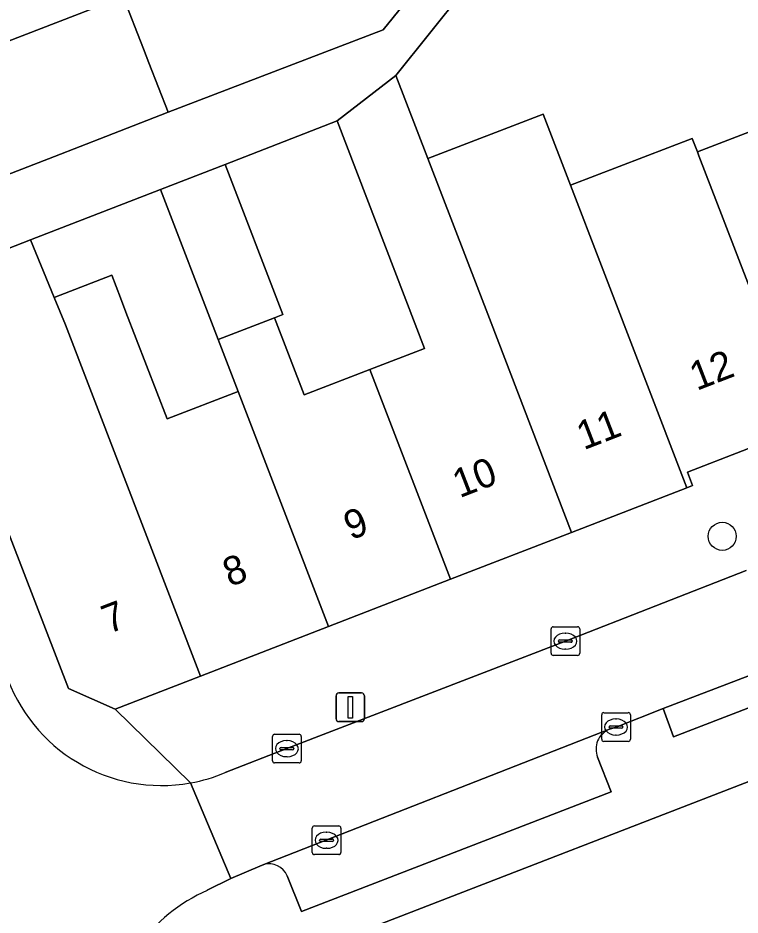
# Model space of a CAD drawing. Extents: x 161692 to 162379, y 380760 to 381678.
# Drawn here: x 161861.55 to 161886.75, y 381122.22 to 381153.51 of the extents above; entities that cross this region are included whole.
import ezdxf

# ---------------------------------------------------------------- set-up
doc = ezdxf.new("R2010")
doc.units = 0
for name, color, linetype in [('IMGEO_Boom', 7, 'Continuous'), ('IMGEO_Erf', 7, 'Continuous'), ('IMGEO_Groenvoorziening', 7, 'Continuous'), ('IMGEO_Kolk', 7, 'Continuous'), ('IMGEO_Lichtmast', 7, 'Continuous'), ('IMGEO_Pand', 7, 'Continuous'), ('IMGEO_Pand_nummerreeks', 7, 'Continuous'), ('IMGEO_Parkeervlak_open', 7, 'Continuous'), ('IMGEO_Rijbaan_lokaal_open', 7, 'Continuous'), ('IMGEO_Voetpad_gesloten', 7, 'Continuous'), ('IMGEO_Voetpad_open', 7, 'Continuous')]:
    doc.layers.add(name, color=color, linetype=linetype)

msp = doc.modelspace()

# ---------------------------------------------------------------- linework, layer by layer
at = {"layer": 'IMGEO_Boom'}
msp.add_circle((161886.126, 381135.429), 0.489, dxfattribs=at)
at = {"layer": 'IMGEO_Erf'}
for points in [[(161865.216, 381154.264), (161865.926, 381152.436), (161866.117, 381151.943), (161866.786, 381150.22), (161874.298, 381153.095), (161886.039, 381167.594)], [(161879.432, 381157.38), (161874.741, 381151.504), (161875.854, 381148.61), (161879.878, 381150.157), (161880.833, 381147.673), (161885.082, 381149.306), (161885.262, 381148.838), (161889.585, 381150.509), (161891.5, 381151.249), (161891.788, 381151.36), (161893.937, 381152.191), (161893.123, 381154.298)]]:
    msp.add_lwpolyline(points, dxfattribs=at)
for points in [[(161872.684, 381149.919), (161868.775, 381148.403), (161870.787, 381143.167), (161870.498, 381143.055), (161871.535, 381140.359), (161873.832, 381141.247), (161875.736, 381141.983)], [(161866.523, 381147.53), (161861.984, 381145.77), (161862.817, 381143.761), (161864.821, 381144.537), (161865.126, 381143.748), (161865.318, 381143.252), (161866.76, 381139.523), (161869.234, 381140.479), (161868.535, 381142.297)]]:
    msp.add_lwpolyline(points, close=True, dxfattribs=at)
at = {"layer": 'IMGEO_Groenvoorziening'}
msp.add_lwpolyline([(161889.237, 381098.122), (161887.481, 381099.78), (161889.509, 381119.184), (161891.249, 381120.655), (161892.607, 381122.097), (161890.302, 381128.132), (161871.724, 381120.949), (161866.545, 381106.35), (161863.772, 381105.601), (161863.248, 381101.216), (161862.407, 381093.385), (161863.41, 381093.267), (161863.195, 381091.592), (161862.202, 381091.684), (161860.9, 381080.876), (161860.594, 381078.32), (161862.509, 381077.782), (161863.62, 381075.409), (161863.759, 381073.519), (161864.131, 381072.768), (161864.237, 381067.43), (161859.466, 381070.205)], dxfattribs=at)
at = {"layer": 'IMGEO_Kolk'}
for p, q in [((161880.227, 381132.274), (161881.079, 381132.274)), ((161880.152, 381131.348), (161880.152, 381132.2)), ((161880.64, 381132.054), (161880.665, 381132.054)), ((161881.153, 381132.2), (161881.153, 381131.348)), ((161880.411, 381131.768), (161880.411, 381131.78)), ((161880.849, 381131.731), (161880.451, 381131.731)), ((161880.454, 381131.817), (161880.852, 381131.817)), ((161880.895, 381131.78), (161880.895, 381131.768)), ((161880.663, 381131.494), (161880.638, 381131.494)), ((161881.079, 381131.274), (161880.227, 381131.274)), ((161881.919, 381128.351), (161881.919, 381129.203)), ((161881.994, 381129.277), (161882.846, 381129.277)), ((161882.92, 381129.203), (161882.92, 381128.351)), ((161882.221, 381128.82), (161882.619, 381128.82)), ((161882.407, 381129.057), (161882.432, 381129.057)), ((161870.507, 381128.522), (161871.359, 381128.522)), ((161882.178, 381128.771), (161882.178, 381128.783)), ((161882.616, 381128.734), (161882.218, 381128.734)), ((161882.662, 381128.783), (161882.662, 381128.771)), ((161870.432, 381127.596), (161870.432, 381128.448)), ((161870.92, 381128.302), (161870.945, 381128.302)), ((161871.433, 381128.448), (161871.433, 381127.596)), ((161882.846, 381128.277), (161881.994, 381128.277)), ((161882.43, 381128.497), (161882.405, 381128.497)), ((161870.691, 381128.016), (161870.691, 381128.028)), ((161871.129, 381127.979), (161870.731, 381127.979)), ((161870.734, 381128.065), (161871.132, 381128.065)), ((161871.175, 381128.028), (161871.175, 381128.016)), ((161870.943, 381127.742), (161870.918, 381127.742)), ((161871.359, 381127.522), (161870.507, 381127.522)), ((161871.817, 381124.399), (161871.817, 381125.251)), ((161871.892, 381125.325), (161872.744, 381125.325)), ((161872.305, 381125.105), (161872.33, 381125.105)), ((161872.818, 381125.251), (161872.818, 381124.399)), ((161872.076, 381124.819), (161872.076, 381124.831)), ((161872.514, 381124.782), (161872.116, 381124.782)), ((161872.119, 381124.868), (161872.517, 381124.868)), ((161872.56, 381124.831), (161872.56, 381124.819)), ((161872.328, 381124.545), (161872.303, 381124.545)), ((161872.744, 381124.325), (161871.892, 381124.325))]:
    msp.add_line(p, q, dxfattribs=at)
for points in [[(161880.227, 381132.274), (161881.079, 381132.274)], [(161880.152, 381131.348), (161880.152, 381132.2)], [(161881.153, 381132.2), (161881.153, 381131.348)], [(161881.079, 381131.274), (161880.227, 381131.274)], [(161881.919, 381128.351), (161881.919, 381129.203)], [(161881.994, 381129.277), (161882.846, 381129.277)], [(161882.92, 381129.203), (161882.92, 381128.351)], [(161870.507, 381128.522), (161871.359, 381128.522)], [(161870.432, 381127.596), (161870.432, 381128.448)], [(161871.433, 381128.448), (161871.433, 381127.596)], [(161882.846, 381128.277), (161881.994, 381128.277)], [(161871.359, 381127.522), (161870.507, 381127.522)], [(161871.817, 381124.399), (161871.817, 381125.251)], [(161871.892, 381125.325), (161872.744, 381125.325)], [(161872.818, 381125.251), (161872.818, 381124.399)], [(161872.744, 381124.325), (161871.892, 381124.325)]]:
    msp.add_lwpolyline(points, dxfattribs=at)
for centre, radius, start, end in [((161880.229, 381132.198), 0.0765, 91.552, 178.448), ((161880.229, 381132.198), 0.0765, 91.552, 178.448), ((161881.077, 381132.198), 0.0765, 1.552, 88.448), ((161881.077, 381132.198), 0.0765, 1.552, 88.448), ((161880.451, 381131.777), 0.0403, 85.8775, 175.7526), ((161880.448, 381131.767), 0.0366, 178.938, 274.7102), ((161880.852, 381131.774), 0.043, 264.8664, 352.4533), ((161880.856, 381131.779), 0.0386, 1.7309, 96.639), ((161880.229, 381131.35), 0.0765, 181.552, 268.448), ((161880.229, 381131.35), 0.0765, 181.552, 268.448), ((161881.077, 381131.35), 0.0765, 271.552, 358.448), ((161881.077, 381131.35), 0.0765, 271.552, 358.448), ((161881.996, 381129.201), 0.0765, 91.552, 178.448), ((161881.996, 381129.201), 0.0765, 91.552, 178.448), ((161882.844, 381129.201), 0.0765, 1.552, 88.448), ((161882.844, 381129.201), 0.0765, 1.552, 88.448), ((161882.218, 381128.78), 0.0403, 85.8775, 175.7526), ((161882.623, 381128.782), 0.0386, 1.7309, 96.639), ((161870.509, 381128.446), 0.0765, 91.552, 178.448), ((161870.509, 381128.446), 0.0765, 91.552, 178.448), ((161871.357, 381128.446), 0.0765, 1.552, 88.448), ((161871.357, 381128.446), 0.0765, 1.552, 88.448), ((161882.215, 381128.77), 0.0366, 178.938, 274.7102), ((161882.619, 381128.777), 0.043, 264.8664, 352.4533), ((161881.996, 381128.353), 0.0765, 181.552, 268.448), ((161881.996, 381128.353), 0.0765, 181.552, 268.448), ((161882.844, 381128.353), 0.0765, 271.552, 358.448), ((161882.844, 381128.353), 0.0765, 271.552, 358.448), ((161870.731, 381128.025), 0.0403, 85.8775, 175.7526), ((161870.728, 381128.015), 0.0366, 178.938, 274.7102), ((161871.132, 381128.022), 0.043, 264.8664, 352.4533), ((161871.136, 381128.027), 0.0386, 1.7309, 96.639), ((161870.509, 381127.598), 0.0765, 181.552, 268.448), ((161870.509, 381127.598), 0.0765, 181.552, 268.448), ((161871.357, 381127.598), 0.0765, 271.552, 358.448), ((161871.357, 381127.598), 0.0765, 271.552, 358.448), ((161871.894, 381125.249), 0.0765, 91.552, 178.448), ((161871.894, 381125.249), 0.0765, 91.552, 178.448), ((161872.742, 381125.249), 0.0765, 1.552, 88.448), ((161872.742, 381125.249), 0.0765, 1.552, 88.448), ((161872.116, 381124.828), 0.0403, 85.8775, 175.7526), ((161872.113, 381124.818), 0.0366, 178.938, 274.7102), ((161872.517, 381124.825), 0.043, 264.8664, 352.4533), ((161872.521, 381124.83), 0.0386, 1.7309, 96.639), ((161871.894, 381124.401), 0.0765, 181.552, 268.448), ((161871.894, 381124.401), 0.0765, 181.552, 268.448), ((161872.742, 381124.401), 0.0765, 271.552, 358.448), ((161872.742, 381124.401), 0.0765, 271.552, 358.448)]:
    msp.add_arc(centre, radius, start, end, dxfattribs=at)
for centre, major_axis, ratio, start_param, end_param in [((161880.639, 381131.774), (-0.387, 0.002), 0.722429, 4.712389, 7.853982), ((161880.664, 381131.774), (-0.39, 0.002), 0.717154, 1.570796, 4.712389), ((161882.406, 381128.777), (-0.387, 0.002), 0.722429, 4.712389, 7.853982), ((161882.431, 381128.777), (-0.39, 0.002), 0.717154, 1.570796, 4.712389), ((161870.919, 381128.022), (-0.387, 0.002), 0.722429, 4.712389, 7.853982), ((161870.944, 381128.022), (-0.39, 0.002), 0.717154, 1.570796, 4.712389), ((161872.304, 381124.825), (-0.387, 0.002), 0.722429, 4.712389, 7.853982), ((161872.329, 381124.825), (-0.39, 0.002), 0.717154, 1.570796, 4.712389)]:
    msp.add_ellipse(centre, major_axis=major_axis, ratio=ratio, start_param=start_param, end_param=end_param, dxfattribs=at)
at = {"layer": 'IMGEO_Lichtmast'}
for p, q in [((161872.651, 381129.066), (161872.651, 381129.866)), ((161872.651, 381129.866), (161872.651, 381129.066)), ((161872.751, 381129.966), (161873.541, 381129.966)), ((161873.541, 381129.966), (161872.751, 381129.966)), ((161873.641, 381129.866), (161873.641, 381129.066)), ((161873.641, 381129.066), (161873.641, 381129.866)), ((161873.541, 381128.966), (161872.751, 381128.966)), ((161872.751, 381128.966), (161873.541, 381128.966))]:
    msp.add_line(p, q, dxfattribs=at)
msp.add_lwpolyline([(161873.071, 381129.841), (161873.221, 381129.841), (161873.221, 381129.091), (161873.071, 381129.091), (161873.071, 381129.841)], dxfattribs=at)
for centre, start, end in [((161872.751, 381129.866), 90, 180), ((161872.751, 381129.866), 90, 180), ((161873.541, 381129.866), 0, 90), ((161873.541, 381129.866), 360, 90), ((161872.751, 381129.066), 180, 270), ((161872.751, 381129.066), 180, 270), ((161873.541, 381129.066), 270, 0), ((161873.541, 381129.066), 270, 0)]:
    msp.add_arc(centre, 0.1, start, end, dxfattribs=at)
at = {"layer": 'IMGEO_Pand'}
for points in [[(161853.223, 381156.241), (161855.451, 381150.483), (161865.216, 381154.264), (161864.766, 381155.425), (161865.389, 381156.97), (161864.704, 381158.737), (161863.819, 381159.013), (161863.374, 381160.161), (161858.668, 381158.344)], [(161865.216, 381154.264), (161855.451, 381150.483), (161857.147, 381146.103), (161858.29, 381146.546), (161858.163, 381146.874), (161862.825, 381148.683), (161864.611, 381149.376), (161866.786, 381150.22), (161866.117, 381151.943), (161865.926, 381152.436)], [(161875.854, 381148.61), (161874.741, 381151.504), (161872.684, 381149.919), (161875.736, 381141.983), (161873.832, 381141.247), (161876.645, 381133.93), (161880.871, 381135.564), (161878.057, 381142.88)], [(161889.585, 381150.509), (161885.262, 381148.838), (161885.29, 381148.766), (161885.313, 381148.706), (161886.16, 381146.503), (161889.145, 381138.744), (161891.289, 381139.573), (161893.483, 381140.422), (161890.933, 381147.02), (161890.729, 381147.549)], [(161880.833, 381147.673), (161879.878, 381150.157), (161875.854, 381148.61), (161878.057, 381142.88), (161880.871, 381135.564), (161884.891, 381137.118), (161881.914, 381144.861)], [(161885.262, 381148.838), (161885.082, 381149.306), (161880.833, 381147.673), (161881.914, 381144.861), (161884.891, 381137.118), (161885.092, 381137.196), (161884.909, 381137.67), (161888.752, 381139.156), (161888.942, 381138.666), (161889.145, 381138.744), (161886.16, 381146.503), (161885.313, 381148.706), (161885.29, 381148.766)], [(161868.775, 381148.403), (161866.523, 381147.53), (161868.535, 381142.297), (161870.498, 381143.055), (161870.787, 381143.167)], [(161862.817, 381143.761), (161861.984, 381145.77), (161859.027, 381144.626), (161858.947, 381144.831), (161857.799, 381144.387), (161863.314, 381130.126), (161864.944, 381129.405), (161867.917, 381130.555), (161863.207, 381142.809)], [(161869.234, 381140.479), (161866.76, 381139.523), (161865.318, 381143.252), (161865.126, 381143.748), (161864.821, 381144.537), (161862.817, 381143.761), (161863.207, 381142.809), (161867.917, 381130.555), (161872.385, 381132.282)], [(161873.832, 381141.247), (161871.535, 381140.359), (161870.498, 381143.055), (161868.535, 381142.297), (161869.234, 381140.479), (161872.385, 381132.282), (161876.645, 381133.93)]]:
    msp.add_lwpolyline(points, close=True, dxfattribs=at)
at = {"layer": 'IMGEO_Parkeervlak_open'}
for points in [[(161882.194, 381128.7), (161870.125, 381123.977)], [(161882.245, 381126.518), (161881.772, 381127.73)], [(161870.947, 381123.585), (161871.442, 381122.337), (161882.245, 381126.518)]]:
    msp.add_lwpolyline(points, dxfattribs=at)
for centre, radius, start, end in [((161882.537, 381127.917), 0.855, 113.6739, 154.1333), ((161882.66, 381128.016), 0.933, 162.9485, 197.87), ((161870.311, 381123.31), 0.693, 23.4209, 105.5875)]:
    msp.add_arc(centre, radius, start, end, dxfattribs=at)
at = {"layer": 'IMGEO_Rijbaan_lokaal_open'}
for points in [[(161867.569, 381126.828), (161868.98, 381123.492), (161869.994, 381123.926), (161870.125, 381123.977), (161882.194, 381128.7), (161882.42, 381128.777), (161884.067, 381129.426), (161895.325, 381133.728), (161896.277, 381134.132), (161908.638, 381138.85), (161914.271, 381141.027), (161915.464, 381141.487), (161935.2, 381149.114)], [(161886.961, 381134.235), (161880.653, 381131.774), (161870.933, 381128.022), (161868.781, 381127.188)], [(161868.157, 381123.08), (161868.98, 381123.492), (161867.569, 381126.828)]]:
    msp.add_lwpolyline(points, dxfattribs=at)
for centre, radius, start, end in [((161866.554, 381132.467), 5.729, 198.2131, 280.2019), ((161866.575, 381132.396), 5.656, 280.1256, 292.9604), ((161870.514, 381117.725), 5.85, 113.7563, 175.0812)]:
    msp.add_arc(centre, radius, start, end, dxfattribs=at)
at = {"layer": 'IMGEO_Voetpad_gesloten'}
msp.add_lwpolyline([(161895.707, 381132.787), (161895.325, 381133.728), (161884.067, 381129.426), (161884.427, 381128.432)], close=True, dxfattribs=at)
at = {"layer": 'IMGEO_Voetpad_open'}
for points in [[(161886.039, 381167.594), (161874.298, 381153.095), (161866.786, 381150.22), (161864.611, 381149.376), (161862.825, 381148.683), (161858.163, 381146.874), (161858.29, 381146.546), (161857.147, 381146.103), (161857.799, 381144.387), (161858.947, 381144.831), (161859.027, 381144.626), (161861.984, 381145.77), (161866.523, 381147.53), (161868.775, 381148.403), (161872.684, 381149.919), (161874.741, 381151.504), (161879.432, 381157.38)], [(161867.569, 381126.828), (161864.944, 381129.405), (161863.314, 381130.126), (161857.799, 381144.387), (161857.147, 381146.103), (161855.451, 381150.483), (161853.223, 381156.241)], [(161914.14, 381149.033), (161910.252, 381147.53), (161910.462, 381146.987), (161906.184, 381145.333), (161901.955, 381143.698), (161897.834, 381142.104), (161893.483, 381140.422), (161891.289, 381139.573), (161889.145, 381138.744), (161888.942, 381138.666), (161888.752, 381139.156), (161884.909, 381137.67), (161885.092, 381137.196), (161884.891, 381137.118), (161880.871, 381135.564), (161876.645, 381133.93), (161872.385, 381132.282), (161867.917, 381130.555), (161864.944, 381129.405), (161867.569, 381126.828)], [(161864.685, 381118.227), (161871.724, 381120.949), (161890.302, 381128.132), (161893.576, 381129.276), (161899.888, 381112.731), (161901.747, 381112.421), (161900.087, 381116.686), (161899.472, 381118.111), (161894.749, 381130.245), (161899.582, 381132.126), (161904.11, 381133.888), (161908.792, 381135.71), (161913.272, 381137.454), (161917.928, 381139.266), (161922.709, 381141.126), (161927.336, 381142.927), (161932.118, 381144.788), (161937.71, 381146.964), (161941.26, 381148.346)], [(161880.653, 381131.774), (161886.961, 381134.235)], [(161896.277, 381134.132), (161895.325, 381133.728), (161895.707, 381132.787), (161884.427, 381128.432), (161884.067, 381129.426), (161882.42, 381128.777), (161882.194, 381128.7)], [(161868.781, 381127.188), (161870.933, 381128.022), (161880.653, 381131.774)], [(161881.772, 381127.73), (161882.245, 381126.518), (161871.442, 381122.337), (161870.947, 381123.585)], [(161870.125, 381123.977), (161869.994, 381123.926), (161868.98, 381123.492), (161868.157, 381123.08)]]:
    msp.add_lwpolyline(points, dxfattribs=at)
for centre, radius, start, end in [((161866.554, 381132.467), 5.729, 198.2131, 280.2019), ((161882.537, 381127.917), 0.855, 113.6739, 154.1333), ((161882.66, 381128.016), 0.933, 162.9485, 197.87), ((161866.575, 381132.396), 5.656, 280.1256, 292.9604), ((161870.311, 381123.31), 0.693, 23.4209, 105.5875), ((161870.514, 381117.725), 5.85, 113.7563, 175.0812)]:
    msp.add_arc(centre, radius, start, end, dxfattribs=at)

# ---------------------------------------------------------------- texts
at = {"layer": 'IMGEO_Pand_nummerreeks'}
for s, rotation, p in [('12', 21.1421, (161885.235, 381140.499)), ('11', 21.1409, (161881.291, 381138.428)), ('10', 21.1421, (161876.961, 381136.755)), ('9', 21.1421, (161873.164, 381135.285)), ('8', 21.1421, (161868.943, 381133.654)), ('7', 21.1421, (161864.715, 381132.018))]:
    msp.add_text(s, height=1, rotation=rotation, dxfattribs=at).set_placement(p)

doc.saveas('drawing.dxf')
